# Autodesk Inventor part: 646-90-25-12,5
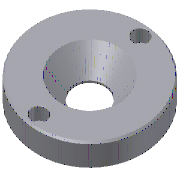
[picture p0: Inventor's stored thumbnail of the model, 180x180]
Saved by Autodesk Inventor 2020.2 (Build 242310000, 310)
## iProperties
Manager: www.cadconsulting.pl
Company: Fabian Stasiak CAD Consulting
Created: 2014-02
Part Number: 646-90-25-12,5
Material: ANFOR XC 38 TS
Description: Locating Ring
Document SubType Name: Modeling
Designer: F.Stasiak
Standard Revision: 1
Manufacturer: RABOURDIN
Language: pl-PL
Size Designation: 646-90-25-12,5
Categories: <MemberInstance><Categories><Category DisplayName="Forma wtryskowa" InternalName="349578f2-f4d4-4954-8c09-8e99297a61c0" Mnemonic="MOLD"><Category DisplayName="E
Density: 7.845 g/cm^3
Appearance: Domyślna
Catalog Web Link: www.expertbooks.pl
IsCustomPart: 1
Author: F.Stasiak
Subject: Zbiór ćwiczeń. Autodesk Inventor 2020. Kurs Professional
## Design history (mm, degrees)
sketch "Sketch1"
  geometry: L1 (0, -2.5)-(0, 15) reference; L2 (24, 12.5)-(12.5, 1); L3 (12.5, 1)-(12.5, 0); L4 (12.5, 0)-(45, 0); L5 (45, 0)-(45, 12.5); L6 (45, 12.5)-(24, 12.5); 1 further point
  constraints: 10 end point, 2 horizontal, 2 vertical, 1 point on line
  dimensions: "d0" = 45 deg angle of L1 L2; "d1" = 25 diameter of L3 L1 (= D2); "d2" = 90 diameter of L5 L1 (= D1); "d3" = 12.5 distance between parallel lines of L4 L6 (= A_); "d4" = 1 distance from line of L2.end L4 (= C_)
revolve "Revolution1" sketch "Sketch1" stored, may be unused: angle "d5" = 90 deg
sketch "Sketch2"
  geometry: 3 further points
  constraints: 2 vertical alignment
  dimensions: "d29" = 37 distance of point (0, 0) point (0, 37); "d30" = 37 distance of point (0, -37) point (0, 0)
hole "Hole1" sketch "Sketch2" diameter "d7" = 7; stored, may be unused: countersink angle "d11" = 90 deg, drill point angle "d13" = 0 deg; dims "d8" = 6, "d9" = 11, "d10" = 7, "d12" = 12.5 (= A_)
hole "Hole2" sketch "Sketch2" diameter "d31" = 7; stored, may be unused: countersink angle "d35" = 90 deg, drill point angle "d37" = 0 deg; dims "d32" = 6, "d33" = 11, "d34" = 7, "d36" = 12.5 (= A_)
chamfer "Chamfer1" distance "d14" = 1; stored, may be unused: second distance "d15" = 2, angle "d16" = 45 deg
chamfer "Chamfer2" distance "d17" = 0.5; stored, may be unused: second distance "d18" = 2, angle "d19" = 45 deg
chamfer "Chamfer3" distance "d20" = 0.3; stored, may be unused: second distance "d21" = 2, angle "d22" = 45 deg
sketch "Sketch3"
  geometry: L1 (0, -2.5)-(0, 15) reference; L2 (0, 0)-(45, 0); L3 (45, 0)-(45, 12.5); L4 (45, 12.5)-(0, 12.5); L5 (0, 12.5)-(0, 0)
  constraints: 8 end point, 2 parallel, 1 horizontal, 1 perpendicular
  dimensions: "d23" = 90 diameter of L3 L1 (= D1_CS); "d24" = 12.5 distance between parallel lines of L2 L4 (= A_CS)
feature "RevolutionSrf1" sketch "Sketch3" dims angle "d25" = 90 deg
body "Solid1"
body "Srf1"
other parameters: "D1" = 90 [user parameter; used in 1 equation term], "D2" = 25 [user parameter; used in 1 equation term], "A_" = 12.5 [user parameter; used in 3 equation terms], "C_" = 1 [user parameter; used in 1 equation term], "D1_CS" = 90 [user parameter; used in 1 equation term], "A_CS" = 12.5 [user parameter; used in 1 equation term], "d26" = 0, "d27" = 0, "d28" = 0
